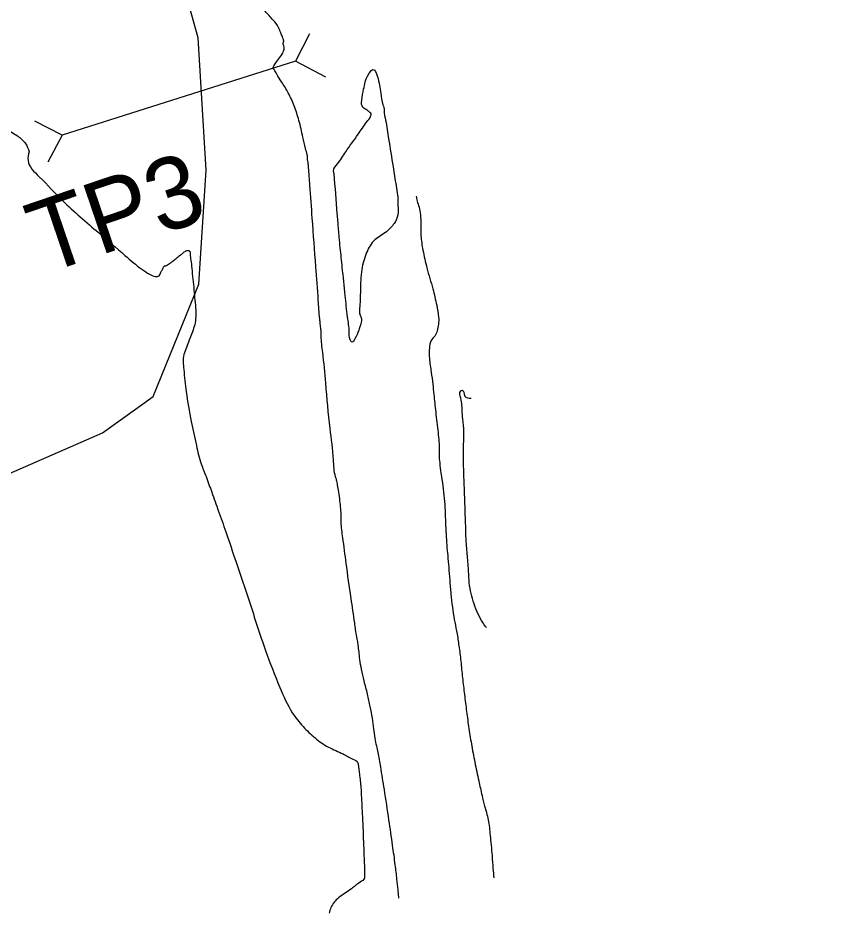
# Model space of a CAD drawing. Extents: x -478645 to -472650, y -1118147 to -1113892.
# Drawn here: x -476220.2 to -476106.8, y -1117141.8 to -1117014.8 of the extents above; entities that cross this region are included whole.
import ezdxf

# ---------------------------------------------------------------- set-up
doc = ezdxf.new("R2010")
doc.units = 0
for name, color, linetype in [('ObPÚ', 7, 'Continuous'), ('TP_stavajicí_mosty', 7, 'Continuous'), ('Vrstevnice_hlavni', 7, 'Continuous'), ('Vrstevnice_vedlejsi', 7, 'Continuous')]:
    doc.layers.add(name, color=color, linetype=linetype)

msp = doc.modelspace()

# ---------------------------------------------------------------- linework, layer by layer
at = {"layer": 'ObPÚ'}
msp.add_lwpolyline([(-476104.79, -1117188.01), (-476125.75, -1117189.99), (-476140.43, -1117190.84), (-476150.96, -1117191.92), (-476159.5, -1117192.77), (-476224.13, -1117203.13), (-476225.41, -1117191.08), (-476226.67, -1117162.34), (-476231.32, -1117146.23), (-476236.27, -1117130.89), (-476246.121, -1117095.624), (-476232.168, -1117082.964), (-476208.459, -1117072.61), (-476201.378, -1117067.542), (-476195.006, -1117051.861), (-476193.973, -1117036.008), (-476195.123, -1117017.563), (-476203.93, -1116985.93)], dxfattribs=at)
at = {"layer": 'TP_stavajicí_mosty'}
for p, q in [((-476179.594, -1117017.011), (-476181.556, -1117020.798)), ((-476181.556, -1117020.798), (-476214.06, -1117031.14)), ((-476181.556, -1117020.798), (-476214.06, -1117031.14)), ((-476177.325, -1117023.028), (-476181.556, -1117020.798)), ((-476214.06, -1117031.14), (-476217.849, -1117029.183)), ((-476214.06, -1117031.14), (-476216.055, -1117034.906))]:
    msp.add_line(p, q, dxfattribs=at)
at = {"layer": 'Vrstevnice_hlavni'}
msp.add_spline([(-476206.652, -1117178.906), (-476206.912, -1117178.348), (-476209.341, -1117173.725), (-476211.536, -1117169.856), (-476213.496, -1117166.739), (-476215.223, -1117164.376), (-476216.372, -1117162.765), (-476216.944, -1117161.906), (-476216.939, -1117161.798), (-476216.948, -1117161.695), (-476216.97, -1117161.597), (-476217.006, -1117161.504), (-476217.035, -1117161.434), (-476217.055, -1117161.387), (-476217.068, -1117161.364), (-476217.869, -1117160.487), (-476219.458, -1117158.755), (-476221.836, -1117156.168), (-476224.025, -1117153.59), (-476226.026, -1117151.021), (-476227.839, -1117148.461), (-476229.316, -1117146.439), (-476230.458, -1117144.956), (-476231.265, -1117144.011), (-476231.967, -1117143.022), (-476232.564, -1117141.99), (-476233.057, -1117140.915), (-476233.666, -1117139.839), (-476234.391, -1117138.762), (-476235.231, -1117137.684), (-476235.806, -1117136.941), (-476236.117, -1117136.531), (-476236.162, -1117136.455), (-476236.279, -1117136.467), (-476236.468, -1117136.566), (-476236.728, -1117136.753), (-476236.903, -1117136.876), (-476236.994, -1117136.936), (-476237.001, -1117136.931), (-476237.008, -1117136.923), (-476237.014, -1117136.912), (-476237.021, -1117136.898), (-476237.036, -1117136.855), (-476237.059, -1117136.783), (-476237.089, -1117136.682), (-476237.266, -1117136.022), (-476237.588, -1117134.805), (-476238.057, -1117133.03), (-476238.423, -1117131.552), (-476238.688, -1117130.371), (-476238.85, -1117129.488), (-476238.979, -1117128.769), (-476239.073, -1117128.213), (-476239.134, -1117127.822), (-476239.32, -1117127.303), (-476239.632, -1117126.656), (-476240.07, -1117125.882), (-476240.487, -1117125.12), (-476240.885, -1117124.371), (-476241.262, -1117123.634), (-476241.579, -1117122.995), (-476241.836, -1117122.453), (-476242.033, -1117122.009), (-476242.251, -1117121.588), (-476242.49, -1117121.19), (-476242.749, -1117120.815), (-476243.08, -1117120.066), (-476243.481, -1117118.944), (-476243.953, -1117117.449), (-476244.291, -1117116.381), (-476244.494, -1117115.74), (-476244.561, -1117115.526), (-476244.665, -1117115.217), (-476244.806, -1117114.813), (-476244.984, -1117114.313), (-476245.236, -1117113.882), (-476245.562, -1117113.52), (-476245.962, -1117113.226), (-476246.483, -1117112.711), (-476247.125, -1117111.974), (-476247.888, -1117111.015), (-476248.249, -1117110.238), (-476248.209, -1117109.642), (-476247.766, -1117109.227), (-476247.681, -1117108.981), (-476247.952, -1117108.903), (-476248.581, -1117108.994), (-476249.094, -1117108.824), (-476249.493, -1117108.392)], degree=3, dxfattribs=at)
at = {"layer": 'Vrstevnice_vedlejsi'}
for points in [[(-476316.243, -1116908.48), (-476314.561, -1116908.998), (-476313.123, -1116909.665), (-476311.928, -1116910.479), (-476310.975, -1116911.441), (-476307.447, -1116912.926), (-476301.342, -1116914.935), (-476292.661, -1116917.468), (-476286.431, -1116920.344), (-476282.653, -1116923.565), (-476281.326, -1116927.13), (-476278.825, -1116928.622), (-476275.148, -1116928.043), (-476270.296, -1116925.391), (-476267.359, -1116923.353), (-476266.337, -1116921.926), (-476267.229, -1116921.113), (-476266.831, -1116920.277), (-476265.141, -1116919.419), (-476262.159, -1116918.539), (-476258.731, -1116917.573), (-476254.857, -1116916.522), (-476250.536, -1116915.385), (-476247.506, -1116914.708), (-476245.767, -1116914.49), (-476245.318, -1116914.73), (-476244.967, -1116914.931), (-476244.714, -1116915.09), (-476244.558, -1116915.209), (-476244.297, -1116915.426), (-476243.929, -1116915.74), (-476243.455, -1116916.152), (-476242.992, -1116916.618), (-476242.539, -1116917.137), (-476242.097, -1116917.711), (-476241.648, -1116918.268), (-476241.19, -1116918.809), (-476240.724, -1116919.335), (-476240.357, -1116919.802), (-476240.09, -1116920.212), (-476239.921, -1116920.565), (-476239.776, -1116920.901), (-476239.653, -1116921.22), (-476239.554, -1116921.522), (-476239.275, -1116922.323), (-476238.817, -1116923.622), (-476238.18, -1116925.419), (-476237.671, -1116926.892), (-476237.289, -1116928.04), (-476237.035, -1116928.865), (-476237.012, -1116929.601), (-476237.222, -1116930.251), (-476237.665, -1116930.812), (-476238.042, -1116931.305), (-476238.354, -1116931.728), (-476238.601, -1116932.083), (-476239.32, -1116932.842), (-476240.511, -1116934.008), (-476242.173, -1116935.579), (-476243.89, -1116939.165), (-476245.66, -1116944.767), (-476247.485, -1116952.383), (-476247.667, -1116959.217), (-476246.206, -1116965.267), (-476243.103, -1116970.535), (-476240.745, -1116976.442), (-476239.133, -1116982.988), (-476238.266, -1116990.175), (-476237.639, -1116995.076), (-476237.25, -1116997.694), (-476237.099, -1116998.028), (-476236.956, -1116998.362), (-476236.818, -1116998.698), (-476236.687, -1116999.033), (-476236.643, -1116999.341), (-476236.684, -1116999.621), (-476236.813, -1116999.873), (-476235.592, -1117002.993), (-476233.023, -1117008.983), (-476229.104, -1117017.842), (-476226.381, -1117023.996), (-476224.854, -1117027.447), (-476224.521, -1117028.193), (-476224.304, -1117028.701), (-476224.204, -1117028.973), (-476224.22, -1117029.007), (-476224.213, -1117029.062), (-476224.183, -1117029.137), (-476224.131, -1117029.234), (-476224.075, -1117029.288), (-476224.014, -1117029.297), (-476223.948, -1117029.262), (-476223.307, -1117029.574), (-476222.09, -1117030.231), (-476220.296, -1117031.233), (-476219.154, -1117032.301), (-476218.662, -1117033.435)], [(-476179.724, -1117035.627), (-476179.75, -1117035.303), (-476179.782, -1117035.021), (-476179.82, -1117034.78), (-476179.865, -1117034.582), (-476179.89, -1117034.419), (-476179.894, -1117034.292), (-476179.878, -1117034.199), (-476179.879, -1117034.093), (-476179.896, -1117033.973), (-476179.929, -1117033.839), (-476180.135, -1117032.979), (-476180.515, -1117031.393), (-476181.068, -1117029.081), (-476181.748, -1117027.028), (-476182.554, -1117025.234), (-476183.488, -1117023.699), (-476184.151, -1117022.618), (-476184.543, -1117021.993), (-476184.665, -1117021.823), (-476184.551, -1117021.459), (-476184.202, -1117020.899), (-476183.616, -1117020.145), (-476183.252, -1117019.523), (-476183.11, -1117019.034), (-476183.19, -1117018.678), (-476183.244, -1117018.432), (-476183.271, -1117018.296), (-476183.272, -1117018.269), (-476183.261, -1117018.232), (-476183.237, -1117018.185), (-476183.201, -1117018.126), (-476183.188, -1117018.039), (-476183.199, -1117017.923), (-476183.234, -1117017.779), (-476183.365, -1117017.428), (-476183.592, -1117016.87), (-476183.916, -1117016.106), (-476184.647, -1117015.105), (-476185.785, -1117013.867), (-476187.33, -1117012.392), (-476188.388, -1117011.262), (-476188.958, -1117010.478), (-476189.041, -1117010.039), (-476189.106, -1117009.636), (-476189.153, -1117009.267), (-476189.182, -1117008.935), (-476189.557, -1117008.114), (-476190.278, -1117006.805), (-476191.346, -1117005.008), (-476192.127, -1117003.633), (-476192.621, -1117002.68), (-476192.828, -1117002.148), (-476193.262, -1117001.482), (-476193.923, -1117000.684), (-476194.811, -1116999.752), (-476195.507, -1116998.877), (-476196.011, -1116998.058), (-476196.323, -1116997.295), (-476196.58, -1116996.639), (-476196.782, -1116996.088), (-476196.93, -1116995.644), (-476197.398, -1116994.17), (-476198.187, -1116991.667), (-476199.296, -1116988.134), (-476200.094, -1116985.612), (-476200.58, -1116984.1), (-476200.756, -1116983.599), (-476200.905, -1116983.191), (-476201.028, -1116982.876), (-476201.124, -1116982.653), (-476201.204, -1116982.463), (-476201.268, -1116982.305), (-476201.315, -1116982.181), (-476202.111, -1116980.963), (-476203.654, -1116978.651), (-476205.945, -1116975.246), (-476207.511, -1116972.904), (-476208.351, -1116971.625), (-476208.466, -1116971.41), (-476208.609, -1116971.129), (-476208.78, -1116970.784), (-476208.979, -1116970.373), (-476209.684, -1116969.095), (-476210.895, -1116966.948), (-476212.612, -1116963.934), (-476214.062, -1116961.433), (-476215.245, -1116959.445), (-476216.162, -1116957.97), (-476216.798, -1116956.955), (-476217.154, -1116956.399), (-476217.228, -1116956.303), (-476217.294, -1116956.22), (-476217.349, -1116956.15), (-476217.396, -1116956.094), (-476218.104, -1116955.211), (-476219.474, -1116953.504)], [(-476176.161, -1117036.513), (-476175.718, -1117042.074), (-476175.564, -1117044.01), (-476175.479, -1117045.102), (-476175.461, -1117045.349), (-476175.311, -1117046.825), (-476175.028, -1117049.53), (-476174.614, -1117053.465), (-476174.295, -1117056.457), (-476174.071, -1117058.506), (-476173.943, -1117059.613), (-476173.677, -1117059.948), (-476173.274, -1117059.512), (-476172.734, -1117058.304), (-476172.431, -1117057.352), (-476172.366, -1117056.656), (-476172.538, -1117056.216), (-476172.585, -1117054.93), (-476172.507, -1117052.798), (-476172.304, -1117049.82), (-476171.633, -1117047.459), (-476170.492, -1117045.715), (-476168.883, -1117044.587), (-476167.811, -1117043.42), (-476167.276, -1117042.212), (-476167.277, -1117040.965), (-476167.282, -1117040.123), (-476167.288, -1117039.686), (-476167.298, -1117039.655), (-476167.306, -1117039.615), (-476167.313, -1117039.564), (-476167.319, -1117039.504), (-476167.531, -1117038.16), (-476167.948, -1117035.533), (-476168.572, -1117031.623), (-476168.988, -1117029.013), (-476169.197, -1117027.703), (-476169.197, -1117027.693), (-476169.357, -1117026.885), (-476169.677, -1117025.278), (-476170.156, -1117022.874), (-476170.711, -1117021.98), (-476171.342, -1117022.599), (-476172.05, -1117024.729), (-476172.323, -1117026.279), (-476172.161, -1117027.249), (-476171.565, -1117027.64), (-476171.177, -1117027.959), (-476170.999, -1117028.206), (-476171.029, -1117028.383), (-476171.632, -1117029.313), (-476172.807, -1117030.997), (-476174.556, -1117033.436), (-476175.706, -1117035.133), (-476176.257, -1117036.087), (-476176.161, -1117036.513)], [(-476218.662, -1117033.435), (-476218.822, -1117034.635), (-476217.263, -1117036.911), (-476213.986, -1117040.265), (-476208.992, -1117044.695), (-476205.309, -1117047.877), (-476202.938, -1117049.809), (-476201.877, -1117050.493), (-476201.083, -1117050.788), (-476200.555, -1117050.695), (-476200.293, -1117050.212), (-476200.099, -1117049.847), (-476199.974, -1117049.597), (-476199.917, -1117049.464), (-476199.835, -1117049.37), (-476199.726, -1117049.313), (-476199.592, -1117049.295), (-476199.387, -1117049.198), (-476199.112, -1117049.021), (-476198.765, -1117048.765), (-476198.307, -1117048.409), (-476197.736, -1117047.953), (-476197.054, -1117047.397), (-476196.575, -1117047.173), (-476196.299, -1117047.28), (-476196.227, -1117047.719), (-476196.128, -1117048.519), (-476196.001, -1117049.68), (-476195.846, -1117051.202), (-476195.702, -1117052.674), (-476195.567, -1117054.097), (-476195.442, -1117055.471), (-476195.474, -1117056.701), (-476195.663, -1117057.787), (-476196.008, -1117058.731), (-476196.365, -1117059.696), (-476196.731, -1117060.685), (-476197.109, -1117061.695), (-476197.123, -1117063.752), (-476196.775, -1117066.855), (-476196.063, -1117071.005), (-476195.366, -1117074.361), (-476194.682, -1117076.923), (-476194.013, -1117078.692), (-476193.219, -1117080.86), (-476192.302, -1117083.427), (-476191.26, -1117086.392), (-476189.817, -1117090.625), (-476187.973, -1117096.125), (-476185.729, -1117102.894), (-476183.735, -1117108.045), (-476181.992, -1117111.578), (-476180.498, -1117113.494), (-476178.823, -1117115.088), (-476176.965, -1117116.361), (-476174.925, -1117117.312), (-476173.551, -1117118.042), (-476172.843, -1117118.55), (-476172.8, -1117118.837), (-476172.731, -1117119.351), (-476172.637, -1117120.093), (-476172.517, -1117121.062), (-476172.381, -1117123.052), (-476172.229, -1117126.063), (-476172.059, -1117130.096), (-476171.954, -1117132.864), (-476171.913, -1117134.367), (-476171.937, -1117134.606), (-476172.55, -1117135.185), (-476173.752, -1117136.105), (-476175.544, -1117137.365), (-476176.609, -1117138.711), (-476176.875, -1117139.506)], [(-476167.154, -1117137.424), (-476167.161, -1117137.225), (-476167.247, -1117136.247), (-476167.406, -1117134.768), (-476167.64, -1117132.789), (-476168.012, -1117130.045), (-476168.521, -1117126.535), (-476169.167, -1117122.259), (-476169.669, -1117119.115), (-476170.025, -1117117.1), (-476170.236, -1117116.217), (-476170.442, -1117115.129), (-476170.643, -1117113.838), (-476170.838, -1117112.343), (-476171.127, -1117110.728), (-476171.51, -1117108.993), (-476171.987, -1117107.138), (-476172.343, -1117105.532), (-476172.58, -1117104.177), (-476172.697, -1117103.072), (-476172.807, -1117102.176), (-476172.909, -1117101.489), (-476173.004, -1117101.011), (-476173.299, -1117099.062), (-476173.794, -1117095.642), (-476174.488, -1117090.75), (-476174.951, -1117087.207), (-476175.181, -1117085.013), (-476175.18, -1117084.167), (-476175.236, -1117083.188), (-476175.348, -1117082.077), (-476175.517, -1117080.833), (-476175.674, -1117079.86), (-476175.821, -1117079.16), (-476175.956, -1117078.731), (-476176.254, -1117076.34), (-476176.715, -1117071.985), (-476177.338, -1117065.667), (-476177.752, -1117061.381), (-476177.957, -1117059.126), (-476177.954, -1117058.902), (-476177.964, -1117058.642), (-476177.989, -1117058.344), (-476178.028, -1117058.009), (-476178.071, -1117057.621), (-476178.119, -1117057.181), (-476178.171, -1117056.687), (-476178.37, -1117054.109), (-476178.715, -1117049.446), (-476179.207, -1117042.699), (-476179.543, -1117038.092), (-476179.724, -1117035.627)], [(-476164.738, -1117039.618), (-476164.589, -1117040.298), (-476164.326, -1117041.14), (-476164.151, -1117042.226), (-476164.062, -1117043.554), (-476164.06, -1117045.125), (-476163.785, -1117047.145), (-476163.236, -1117049.615), (-476162.414, -1117052.533), (-476161.872, -1117054.816), (-476161.609, -1117056.464), (-476161.626, -1117057.476), (-476161.805, -1117058.357), (-476162.145, -1117059.107), (-476162.646, -1117059.726), (-476162.895, -1117060.769), (-476162.892, -1117062.236), (-476162.636, -1117064.128), (-476162.427, -1117065.792), (-476162.265, -1117067.228), (-476162.15, -1117068.436), (-476162.014, -1117069.726), (-476161.857, -1117071.1), (-476161.679, -1117072.556), (-476161.565, -1117073.797), (-476161.516, -1117074.823), (-476161.53, -1117075.635), (-476161.452, -1117076.765), (-476161.282, -1117078.213), (-476161.02, -1117079.978), (-476160.827, -1117081.715), (-476160.704, -1117083.424), (-476160.65, -1117085.104), (-476160.571, -1117086.708), (-476160.468, -1117088.238), (-476160.341, -1117089.693), (-476160.203, -1117091.313), (-476160.056, -1117093.096), (-476159.9, -1117095.044), (-476159.688, -1117096.874), (-476159.423, -1117098.585), (-476159.103, -1117100.177), (-476158.81, -1117102.014), (-476158.544, -1117104.095), (-476158.304, -1117106.421), (-476158.038, -1117108.76), (-476157.747, -1117111.115), (-476157.43, -1117113.483), (-476157.035, -1117115.932), (-476156.562, -1117118.46), (-476156.012, -1117121.068), (-476155.555, -1117123.114), (-476155.192, -1117124.597), (-476154.924, -1117125.518), (-476154.705, -1117126.505), (-476154.536, -1117127.559), (-476154.417, -1117128.679), (-476154.292, -1117130.005), (-476154.162, -1117131.535), (-476154.026, -1117133.271), (-476153.901, -1117134.584)], [(-476154.938, -1117099.703), (-476155.022, -1117099.605), (-476156.404, -1117097.091), (-476157.223, -1117094.255), (-476157.477, -1117091.097), (-476157.652, -1117088.93), (-476157.747, -1117087.756), (-476157.763, -1117087.573), (-476157.809, -1117086.347), (-476157.886, -1117084.076), (-476157.993, -1117080.762), (-476158.071, -1117078.504), (-476158.121, -1117077.302), (-476158.143, -1117077.157), (-476158.148, -1117076.515), (-476158.136, -1117075.376), (-476158.107, -1117073.739), (-476158.094, -1117072.596), (-476158.097, -1117071.945), (-476158.116, -1117071.786), (-476158.191, -1117071.037), (-476158.32, -1117069.696), (-476158.504, -1117067.763), (-476158.503, -1117066.747), (-476158.317, -1117066.647), (-476157.946, -1117067.462), (-476157.085, -1117067.749)]]:
    msp.add_spline(points, degree=3, dxfattribs=at)

# ---------------------------------------------------------------- texts
at = {"layer": 'TP_stavajicí_mosty'}
msp.add_text('TP3', height=10, rotation=18.78552, dxfattribs=at).set_placement((-476216.63, -1117050.56))

doc.saveas('drawing.dxf')
